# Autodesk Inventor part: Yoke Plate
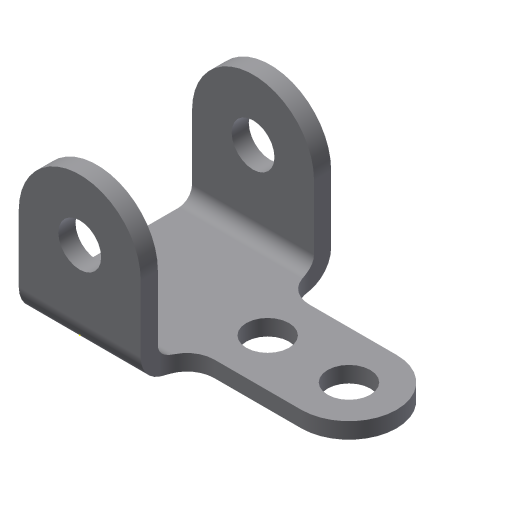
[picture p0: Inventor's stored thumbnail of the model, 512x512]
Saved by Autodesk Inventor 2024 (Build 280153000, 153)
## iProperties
Created: 2011-04
Part Number: Yoke Plate
Material: Generic
Document SubType Name: Modeling
Designer: Dell
Density: 1 g/cm^3
Appearance: Default
Author: Dell
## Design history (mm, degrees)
sketch "Sketch2"
  geometry: L1 (28.5, 36.5)-(28.5, -7.5); L2 (-28.5, -7.5)-(28.5, -7.5); L3 (-28.5, 36.5)-(-28.5, -7.5); C1 r 10 at (0, 36.5); A1 r 28.5 centre (0, 36.5) between (28.5, 36.5) and (-28.5, 36.5); 2 further points
  constraints: 6 end point, 2 centre point, 2 point on circle, 2 tangent, 2 vertical, 1 coincident, 1 perpendicular, 1 other
  dimensions: "d0" = 57 distance of L2.start L1.end; "d1" = 36.5 distance of point (0, 0) C1.centre; "d2" = 28.5 distance from line of L1 point (0, 0); "d3" = 20 diameter of C1; "d24" = 7.5 distance from line of point (0, 0) L2
extrude "Extrusion1" new body sketch "Sketch2" distance "d4" = 89; taper "d5" = 0 deg
sketch "Sketch3"
  geometry: L1 (44, 89)-(0, 89) reference; L2 (-28.588, 8)-(36.5, 8); L3 (36.5, 8)-(36.5, 81); L4 (36.5, 81)-(-28.588, 81); L5 (-28.588, 8)-(-28.588, 81); L6 (-28.5, 89)-(0, 89) reference; 3 further points
  constraints: 8 end point, 1 perpendicular
  dimensions: "d6" = 73 distance of L2.start L4.end; "d9" = 8 distance between parallel lines of L1 L4
extrude "Extrusion2" cut sketch "Sketch3" distance "d10" = 89; taper "d11" = 0 deg
sketch "Sketch4"
  geometry: L1 (0, 58.08)-(53.5, 58.08); L2 (53.5, 13.58)-(0, 13.58); L3 (0, 13.58)-(0, 58.08); L4 (0, 35.83)-(93.365, 35.83); L5 (0, 73)-(0, 0) reference; C1 r 10 at (53.5, 35.83); C2 r 10 at (15.5, 35.83); A1 r 22.25 centre (53.5, 35.83) between (53.5, 13.58) and (53.5, 58.08); 1 further point
  constraints: 8 end point, 3 centre point, 2 horizontal, 2 point on circle, 1 coincident, 1 collinear, 1 equal radius, 1 horizontal alignment, 1 parallel, 1 perpendicular, 1 point on line, 1 tangent
  dimensions: "d12" = 44.5 diameter of A1; "d13" = 44.5 distance between parallel lines of L2 L1; "d14" = 20 diameter of C1; "d15" = 38 distance of A1.centre C2.centre; "d23" = 15.5 distance from line of C2.centre L3
extrude "Extrusion3" join sketch "Sketch4" stored distance "d16" = 89; taper "d17" = 0 deg
fillet "Fillet1" dims "d18" = 12.7
fillet "Fillet2" dims "d19" = 6.35
fillet "Fillet3" dims "d20" = 12.75
body "Solid1"
sketch "Sketch1"
  geometry: 1 further point
